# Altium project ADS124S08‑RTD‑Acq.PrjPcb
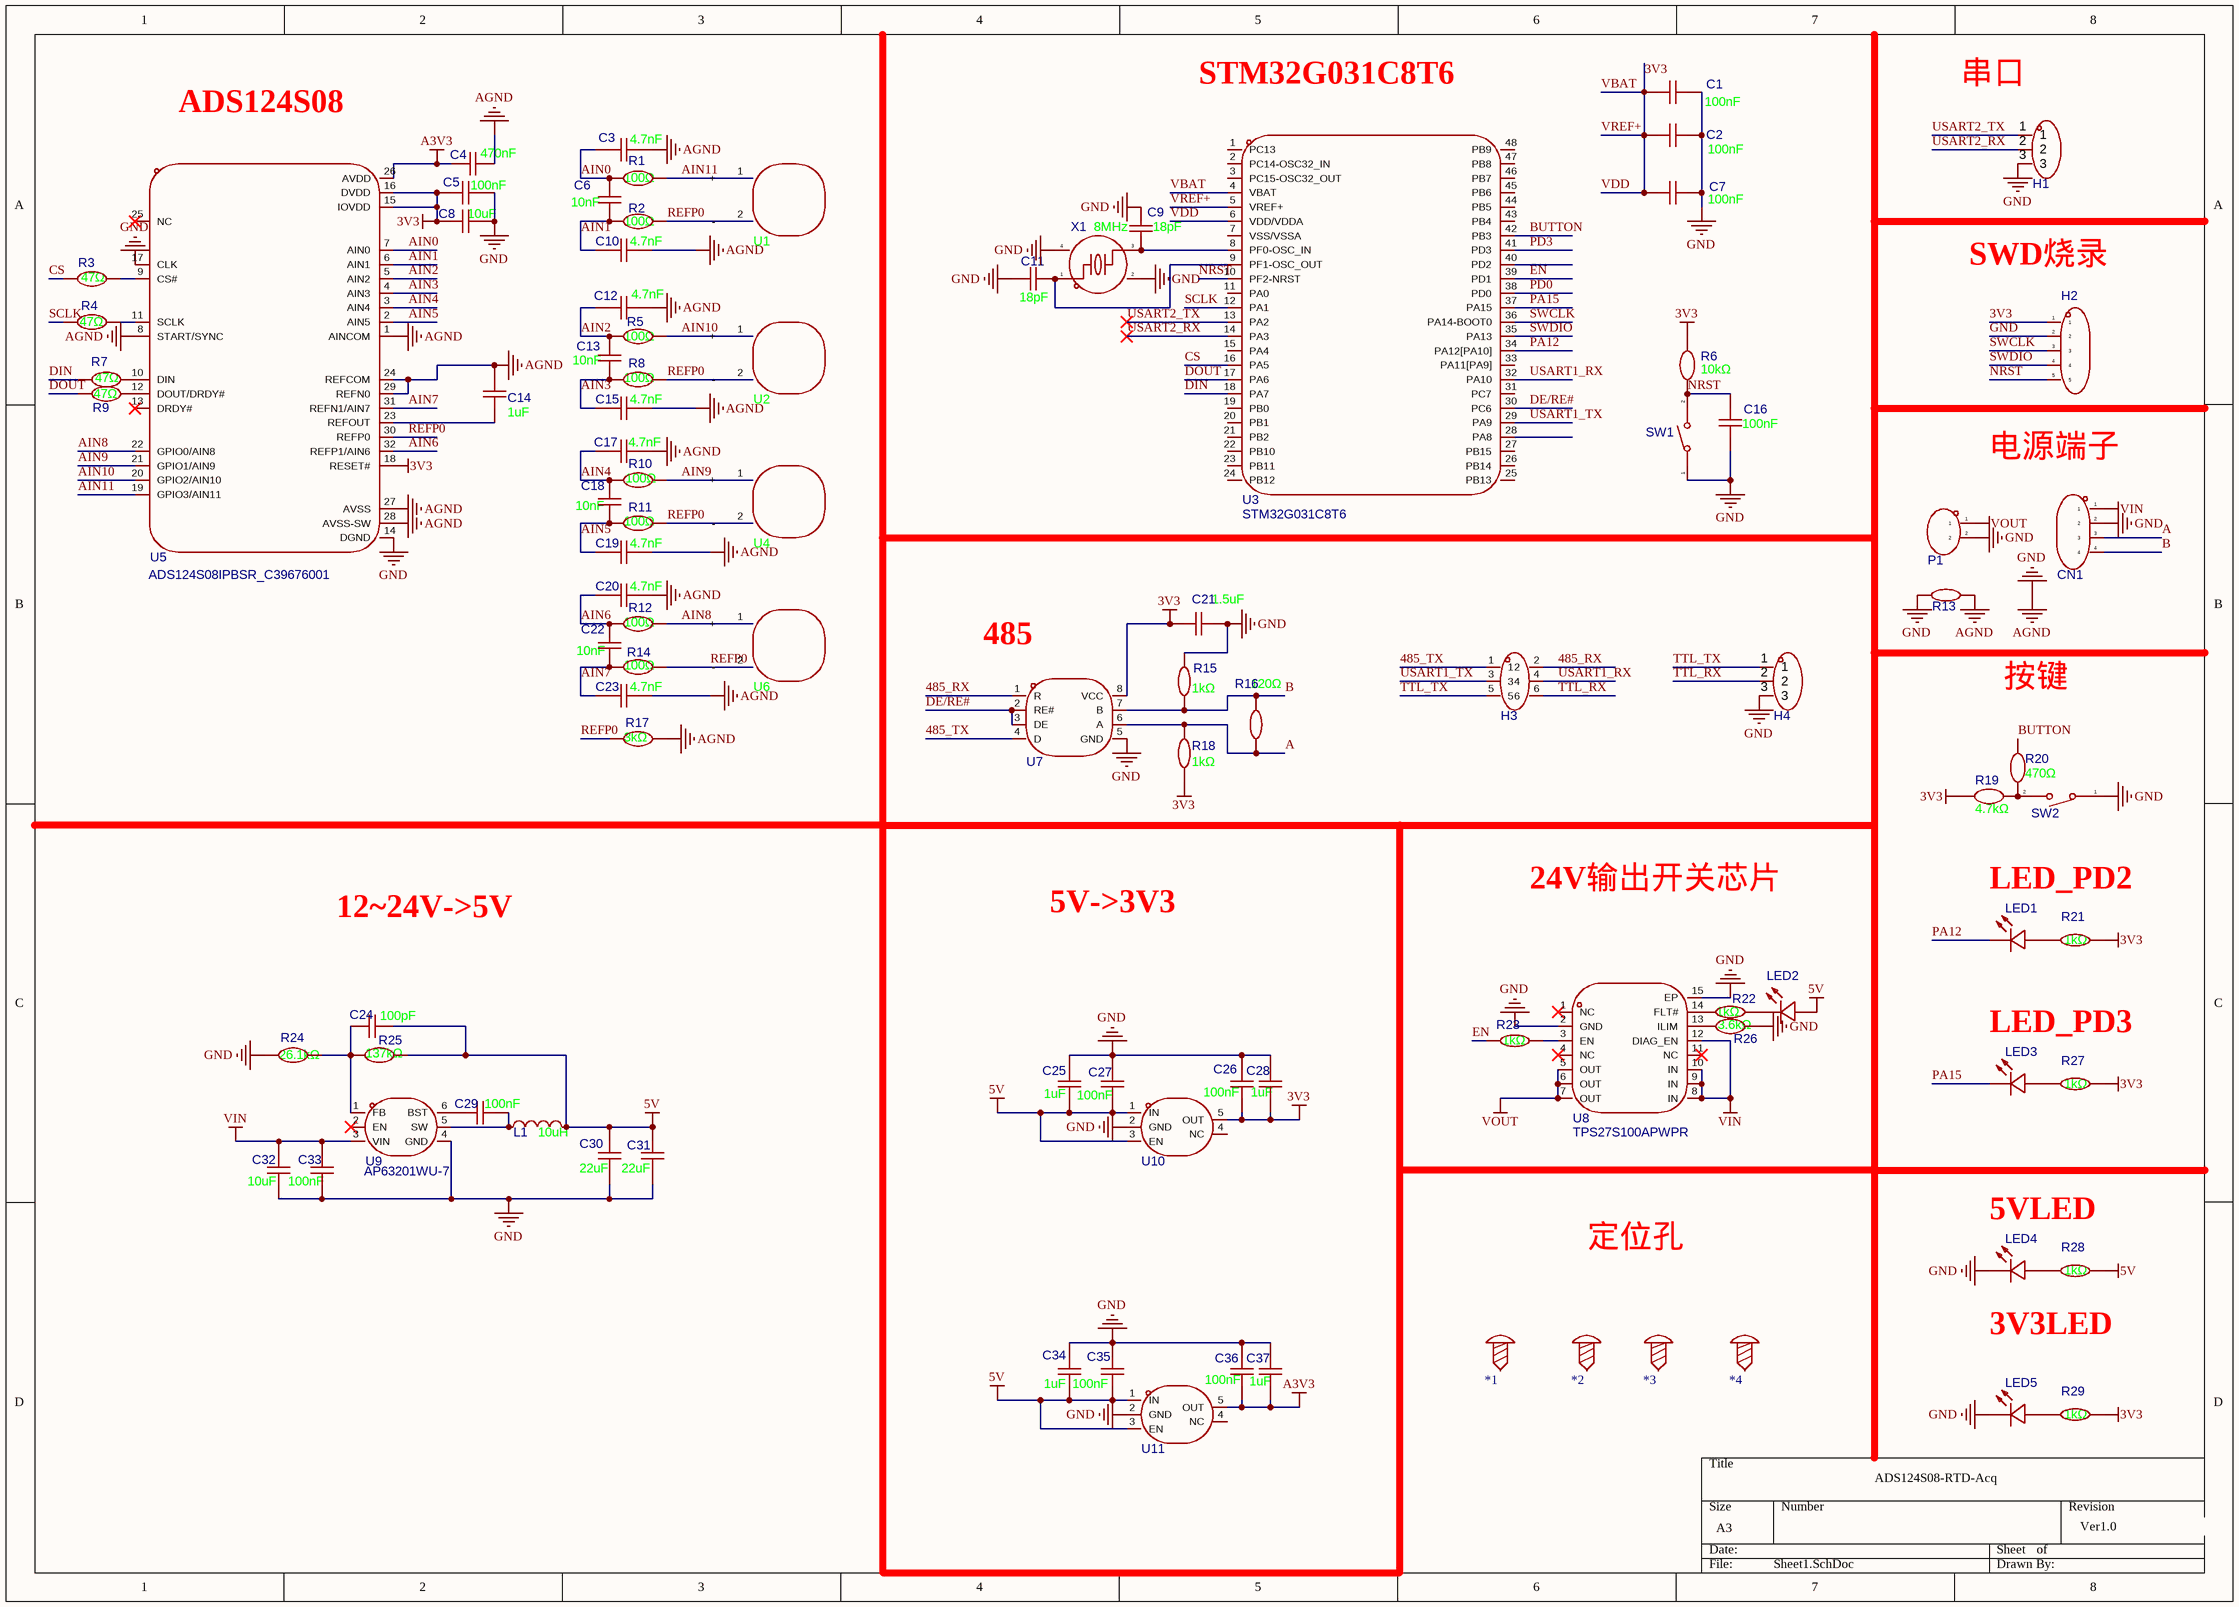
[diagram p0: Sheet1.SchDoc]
1 sheet, 96 parts. Net scope: global (net labels, ports and power ports of the same name join across sheets).
Board file: PCB1.PcbDoc

## Sheet Sheet1.SchDoc
size A3; SheetNumber: 1; SheetTotal: 1

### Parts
*1  螺丝孔_1  [M3螺丝]  (value not drawn)
*2  螺丝孔_1  [M3螺丝]  (value not drawn)
*3  螺丝孔_1  [M3螺丝]  (value not drawn)
*4  螺丝孔_1  [M3螺丝]  (value not drawn)
C1  value 100nF  [C0402]  (hidden comment: cc0402krx7r7bb104)
C2  value 100nF  [C0402]  (hidden comment: cc0402krx7r7bb104)
C3  value 4.7nF  [C0402]  (hidden comment: grm1555c1h472je01d)
C4  value 470nF  [C0603]  (hidden comment: cl10b474ka8nnnc)
C5  value 100nF  [C0402]  (hidden comment: cc0402krx7r7bb104)
C6  value 10nF  [C0805]  (hidden comment: cl21b103kbannnc)
C7  value 100nF  [C0402]  (hidden comment: cc0402krx7r7bb104)
C8  value 10uF  [C0603]  (hidden comment: hgc0603r5106m350nthj)
C9  value 18pF  [C0402]  (hidden comment: cc0402jrnpo9bn180)
C10  value 4.7nF  [C0402]  (hidden comment: grm1555c1h472je01d)
C11  value 18pF  [C0402]  (hidden comment: cc0402jrnpo9bn180)
C12  value 4.7nF  [C0402]  (hidden comment: grm1555c1h472je01d)
C13  value 10nF  [C0805]  (hidden comment: cl21b103kbannnc)
C14  value 1uF  [C0603]  (hidden comment: cga0603x5r105k500jt)
C15  value 4.7nF  [C0402]  (hidden comment: grm1555c1h472je01d)
C16  value 100nF  [C0402]  (hidden comment: cc0402krx7r7bb104)
C17  value 4.7nF  [C0402]  (hidden comment: grm1555c1h472je01d)
C18  value 10nF  [C0805]  (hidden comment: cl21b103kbannnc)
C19  value 4.7nF  [C0402]  (hidden comment: grm1555c1h472je01d)
C20  value 4.7nF  [C0402]  (hidden comment: grm1555c1h472je01d)
C21  value 1.5uF  [C0603]  (hidden comment: c1608x7r1a155kt000e)
C22  value 10nF  [C0805]  (hidden comment: cl21b103kbannnc)
C23  value 4.7nF  [C0402]  (hidden comment: grm1555c1h472je01d)
C24  value 100pF  [C0402]  (hidden comment: cc0402jrnpo9bn101)
C25  value 1uF  [C0603]  (hidden comment: cga0603x5r105k500jt)
C26  value 100nF  [C0402]  (hidden comment: cc0402krx7r7bb104)
C27  value 100nF  [C0402]  (hidden comment: cc0402krx7r7bb104)
C28  value 1uF  [C0603]  (hidden comment: cga0603x5r105k500jt)
C29  value 100nF  [C0603]  (hidden comment: cga0603x7r104k500jt)
C30  value 22uF  [C0603]  (hidden comment: hgc0603r5226m160nthj)
C31  value 22uF  [C0603]  (hidden comment: hgc0603r5226m160nthj)
C32  value 10uF  [C0603]  (hidden comment: hgc0603r5106m350nthj)
C33  value 100nF  [C0603]  (hidden comment: cga0603x7r104k500jt)
C34  value 1uF  [C0603]  (hidden comment: cga0603x5r105k500jt)
C35  value 100nF  [C0402]  (hidden comment: cc0402krx7r7bb104)
C36  value 100nF  [C0402]  (hidden comment: cc0402krx7r7bb104)
C37  value 1uF  [C0603]  (hidden comment: cga0603x5r105k500jt)
CN1  wj15edgrc-3.81-04p-14-00a  [CONN-TH_WJ15EDGRC-3.81-4P]  (value not drawn)
H1  lail-pz2.54-3p-l  [HDR-TH_3P-P2.54-V-M-1]  (value not drawn)
H2  pz254v-11-05p  [HDR-TH_5P-P2.54-V-M]  (value not drawn)
H3  pz254v-12-6p  [HDR-TH_6P-P2.54-V-M-R2-C3-S2.54]  (value not drawn)
H4  lail-pz2.54-3p-l  [HDR-TH_3P-P2.54-V-M-1]  (value not drawn)
L1  value 10uH  [IND-SMD_L4.0-W4.0]  (hidden comment: wpn4020h100mt)
LED1  ltst-c190kskt  [LED0603-RD]  (value not drawn)
LED2  ltst-c190kskt  [LED0603-RD]  (value not drawn)
LED3  ltst-c190kskt  [LED0603-RD]  (value not drawn)
LED4  ltst-c190kskt  [LED0603-RD]  (value not drawn)
LED5  ltst-c190kskt  [LED0603-RD]  (value not drawn)
P1  wj15edgrc-3.81-02p-14-00a  [CONN-TH_2P-P3.81_WJ15EDGRC-3.81-2P]  (value not drawn)
R1  value 100Ω  [R0603]  (hidden comment: frc0603f1000ts)
R2  value 100Ω  [R0603]  (hidden comment: frc0603f1000ts)
R3  value 47Ω  [R0402]  (hidden comment: frc0402f47r0ts)
R4  value 47Ω  [R0402]  (hidden comment: frc0402f47r0ts)
R5  value 100Ω  [R0603]  (hidden comment: frc0603f1000ts)
R6  value 10kΩ  [R0603]  (hidden comment: frc0603f1002ts)
R7  value 47Ω  [R0402]  (hidden comment: frc0402f47r0ts)
R8  value 100Ω  [R0603]  (hidden comment: frc0603f1000ts)
R9  value 47Ω  [R0402]  (hidden comment: frc0402f47r0ts)
R10  value 100Ω  [R0603]  (hidden comment: frc0603f1000ts)
R11  value 100Ω  [R0603]  (hidden comment: frc0603f1000ts)
R12  value 100Ω  [R0603]  (hidden comment: frc0603f1000ts)
R13  0603waf0000t5e  [R0603]  (value not drawn)
R14  value 100Ω  [R0603]  (hidden comment: frc0603f1000ts)
R15  value 1kΩ  [R0402]  (hidden comment: 0402wgf1001tce)
R16  value 120Ω  [R0402]  (hidden comment: 0402wgf1200tce)
R17  value 3kΩ  [R0805]  (hidden comment: frc0805f3001ts)
R18  value 1kΩ  [R0402]  (hidden comment: 0402wgf1001tce)
R19  value 4.7kΩ  [R0603]  (hidden comment: frc0603f4701ts)
R20  value 470Ω  [R0603]  (hidden comment: frc0603j471 ts)
R21  value 1kΩ  [R0603]  (hidden comment: 0603waf1001t5e)
R22  value 1kΩ  [R0603]  (hidden comment: 0603waf1001t5e)
R23  value 1kΩ  [R0603]  (hidden comment: 0603waf1001t5e)
R24  value 26.1kΩ  [R0402]  (hidden comment: rt0402brd0726k1l)
R25  value 137kΩ  [R0402]  (hidden comment: frc0402f1373ts)
R26  value 3.6kΩ  [R0603]  (hidden comment: frc0603f3601ts)
R27  value 1kΩ  [R0603]  (hidden comment: 0603waf1001t5e)
R28  value 1kΩ  [R0603]  (hidden comment: 0603waf1001t5e)
R29  value 1kΩ  [R0603]  (hidden comment: 0603waf1001t5e)
SW1  ts-1088-ar02016  [SW-SMD_L3.9-W3.0-P4.45]  (value not drawn)
SW2  ts-1088-ar02016  [SW-SMD_L3.9-W3.0-P4.45]  (value not drawn)
U1  pt1000焊盘  [PT1000焊盘]  (value not drawn)
U2  pt1000焊盘  [PT1000焊盘]  (value not drawn)
U3  stm32g031c8t6  [LQFP-48_L7.0-W7.0-P0.50-LS9.0-BL]
U4  pt1000焊盘  [PT1000焊盘]  (value not drawn)
U5  ads124s08ipbsr_c39676001  [TQFP-32_L5.0-W5.0-P0.50-LS7.0-BL]
U6  pt1000焊盘  [PT1000焊盘]  (value not drawn)
U7  sn65hvd75dr  [SOIC-8_L4.9-W3.9-P1.27-LS6.0-BL]  (value not drawn)
U8  tps27s100apwpr  [TSSOP-14_L5.0-W4.4-P0.65-LS6.4-BL-EP]
U9  ap63201wu-7  [TSOT-23-6_L2.9-W1.6-P0.95-LS2.8-BR]
U10  tps7a2033pdbvr  [SOT-23-5_L2.9-W1.6-P0.95-LS2.8-BR]  (value not drawn)
U11  tps7a2033pdbvr  [SOT-23-5_L2.9-W1.6-P0.95-LS2.8-BR]  (value not drawn)
X1  value 8MHz  [CRYSTAL-SMD_4P-L3.2-W2.5-BL]  (hidden comment: x32258mob4si)

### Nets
3V3: C1.1 C2.1 C5.2 C7.1 C8.1 C21.2 C26.1 C28.1 H2.1 R6.2 R18.1 R19.2 R21.2 R27.2 R29.2 U3.4(VBAT) U3.5(VREF+) U3.6(VDD/VDDA) U5.15(IOVDD) U5.16(DVDD) U5.18(RESET#) U7.8(VCC) U10.5(OUT)  [also labelled VBAT, VDD, VREF+]
5V: C24.2 C25.1 C27.1 C30.2 C31.2 C34.1 C35.1 L1.2 LED2.2(+) R25.1 R28.2 U10.1(IN) U10.3(EN) U11.1(IN) U11.3(EN)
A3V3: C4.1 C36.1 C37.1 U5.26(AVDD) U11.5(OUT)
GND: C1.2 C2.2 C3.2 C4.2 C5.1 C7.2 C8.2 C9.2 C10.2 C11.1 C12.2 C14.2 C15.2 C16.1 C17.2 C19.2 C20.2 C21.1 C23.2 C25.2 C26.2 C27.2 C28.2 C30.1 C31.1 C32.1 C33.1 C34.2 C35.2 C36.2 C37.2 CN1.2 H1.3 H2.2 H4.3 LED4.1(-) LED5.1(-) P1.2 R13.1 R13.2 R15.2 R17.2 R24.1 R26.2 SW1.1 SW2.1 U5.1(AINCOM) U5.8(START/SYNC) U5.14(DGND) U5.17(CLK) U5.24(REFCOM) U5.27(AVSS) U5.28(AVSS-SW) U5.29(REFN0) U7.5(GND) U8.2(GND) U8.15(EP) U9.4(GND) U10.2(GND) U11.2(GND) X1.2(GND) X1.4(GND)  [also labelled AGND]
VIN: C32.2 C33.2 CN1.1 U8.8(IN) U8.9(IN) U8.10(IN) U8.12(DIAG_EN) U9.3(VIN)
VOUT: P1.1 U8.5(OUT) U8.6(OUT) U8.7(OUT)
485_RX: H3.2 U7.1(R)
485_TX: H3.1 U7.4(D)
A: CN1.3 R16.1 R18.2 U7.6(A)
AIN0: C3.1 C6.2 R1.1 U5.7(AIN0)
AIN1: C6.1 C10.1 R2.1 U5.6(AIN1)
AIN2: C12.1 C13.2 R5.1 U5.5(AIN2)
AIN3: C13.1 C15.1 R8.1 U5.4(AIN3)
AIN4: C17.1 C18.2 R10.1 U5.3(AIN4)
AIN5: C18.1 C19.1 R11.1 U5.2(AIN5)
AIN6: C20.1 C22.2 R12.1 U5.32(REFP1/AIN6)
AIN7: C22.1 C23.1 R14.1 U5.31(REFN1/AIN7)
AIN8: R12.2 U5.22(GPIO0/AIN8) U6.1(+)
AIN9: R10.2 U4.1(+) U5.21(GPIO1/AIN9)
AIN10: R5.2 U2.1(+) U5.20(GPIO2/AIN10)
AIN11: R1.2 U1.1(+) U5.19(GPIO3/AIN11)
B: CN1.4 R15.1 R16.2 U7.7(B)
BUTTON: R20.1 U3.42(PB3)
CS: R3.1 U3.16(PA5)
DE/RE#: U3.30(PC6) U7.2(RE#) U7.3(DE)
DIN: R7.1 U3.18(PA7)
DOUT: R9.1 U3.17(PA6)
EN: R23.1 U3.39(PD1)
NRST: C16.2 H2.5 R6.1 SW1.2 U3.10(PF2-NRST)
PA12: LED1.1(-) U3.34(PA12[PA10])
PA15: LED3.1(-) U3.37(PA15)
PD0: U3.38(PD0)
PD3: U3.41(PD3)
REFP0: R2.2 R8.2 R11.2 R14.2 R17.1 U1.2(-) U2.2(-) U4.2(-) U5.30(REFP0) U6.2(-)
SCLK: R4.1 U3.12(PA1)
SWCLK: H2.3 U3.36(PA14-BOOT0)
SWDIO: H2.4 U3.35(PA13)
TTL_RX: H3.6 H4.2
TTL_TX: H3.5 H4.1
USART1_RX: H3.4 U3.32(PA10)
USART1_TX: H3.3 U3.29(PA9)
USART2_RX: H1.2 U3.14(PA3)
USART2_TX: H1.1 U3.13(PA2)
NetC9_1: C9.1 U3.8(PF0-OSC_IN) X1.3
NetC11_2: C11.2 U3.9(PF1-OSC_OUT) X1.1
NetC14_1: C14.1 U5.23(REFOUT)
NetC24_1: C24.1 R24.2 R25.2 U9.1(FB)
NetC29_1: C29.1 L1.1 U9.5(SW)
NetC29_2: C29.2 U9.6(BST)
NetLED1_2: LED1.2(+) R21.1
NetLED2_1: LED2.1(-) R22.2
NetLED3_2: LED3.2(+) R27.1
NetLED4_2: LED4.2(+) R28.1
NetLED5_2: LED5.2(+) R29.1
NetR3_2: R3.2 U5.9(CS#)
NetR4_2: R4.2 U5.11(SCLK)
NetR7_2: R7.2 U5.10(DIN)
NetR9_2: R9.2 U5.12(DOUT/DRDY#)
NetR19_1: R19.1 R20.2 SW2.2
NetR22_1: R22.1 U8.14(FLT#)
NetR23_2: R23.2 U8.3(EN)
NetR26_1: R26.1 U8.13(ILIM)

Not connected (* = marked no-connect by the designer): *1 1; *2 1; *3 1; *4 1; U3 1(PC13) 2(PC14-OSC32_IN) 3(PC15-OSC32_OUT) 7(VSS/VSSA) 11(PA0) 15(PA4) 19(PB0) 20(PB1) 21(PB2) 22(PB10) 23(PB11) 24(PB12) 25(PB13) 26(PB14) 27(PB15) 28(PA8) 31(PC7) 33(PA11[PA9]) 40(PD2) 43(PB4) 44(PB5) 45(PB6) 46(PB7) 47(PB8) 48(PB9); U5 13(DRDY#)* 25(NC)*; U8 1(NC)* 4(NC)* 11(NC)*; U9 2(EN)*; U10 4(NC); U11 4(NC)

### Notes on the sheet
- ADS124S08
- STM32G031C8T6
- 串口
- SWD烧录
- 电源端子
- (near U7) 485
- 按键
- 24V输出开关芯片
- LED_PD2
- 12|4V->5V
- 5V->3V3
- LED_PD3
- 定位孔
- 5VLED
- 3V3LED
- ADS124S08‑RTD‑Acq
- Ver1.0

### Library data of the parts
C1 C2 C5 C7 C16 C26 C27 C35 C36 = cc0402krx7r7bb104: 容值:100nF;精度:±10%;额定电压:16V;温度系数:X7R;; Manufacturer: YAGEO(国巨); AddInBom: yes; ModelId: 36a51122f27c49738f86b3bfa98863e0; ModelName: C0402_L1.0-W0.5-H0.5; ModelTransform: 39.37,19.685,0,0,0,0,0,0,0; Tolerance: ±10%; Voltage Rating: 16V; Temperature Coefficient: X7R
C3 C10 C12 C15 C17 C19 C20 C23 = grm1555c1h472je01d: 容值:4.7nF;精度:±5%;额定电压:50V;温度系数:C0G;; Manufacturer: muRata(村田); AddInBom: yes; ModelId: 36a51122f27c49738f86b3bfa98863e0; ModelName: C0402_L1.0-W0.5-H0.5; ModelTransform: 39.37,19.685,0,0,0,0,0,0,0; Tolerance: ±5%; Voltage Rating: 50V; Temperature Coefficient: C0G
C4 = cl10b474ka8nnnc: 容值:470nF;精度:±10%;额定电压:25V;温度系数:X7R;; Manufacturer: SAMSUNG(三星); AddInBom: yes; ModelId: ac125912035d415993ca9572d50418b1; ModelName: C0603_L1.6-W0.8-H0.8; ModelTransform: 62.992,31.496,0,0,0,0,0,0,0; Tolerance: ±10%; Voltage Rating: 25V; Temperature Coefficient: X7R
C6 C13 C18 C22 = cl21b103kbannnc: 容值:10nF;精度:±10%;额定电压:50V;温度系数:X7R;; Manufacturer: SAMSUNG(三星); AddInBom: yes; ModelId: 1ba041120af144c991958decab20d241; ModelName: C0805_L2.0-W1.3-H1.3; ModelTransform: 78.74,51.181,0,0,0,0,0,0.0005,0; Tolerance: ±10%; Voltage Rating: 50V; Temperature Coefficient: X7R
C8 C32 = hgc0603r5106m350nthj: 容值:10uF;精度:±20%;额定电压:35V;温度系数:X5R;; Manufacturer: Chinocera(华瓷); AddInBom: yes; ModelId: ac125912035d415993ca9572d50418b1; ModelName: C0603_L1.6-W0.8-H0.8; ModelTransform: 62.992,31.496,0,0,0,0,0,0,0; Tolerance: ±20%; Voltage Rating: 35V; Temperature Coefficient: X5R
C9 C11 = cc0402jrnpo9bn180: 容值:18pF;精度:±5%;额定电压:50V;温度系数:NP0;; Manufacturer: YAGEO(国巨); AddInBom: yes; ModelId: 36a51122f27c49738f86b3bfa98863e0; ModelName: C0402_L1.0-W0.5-H0.5; ModelTransform: 39.37,19.685,0,0,0,0,0,0,0; Tolerance: ±5%; Voltage Rating: 50V; Temperature Coefficient: NP0
C14 C25 C28 C34 C37 = cga0603x5r105k500jt: 容值:1uF;精度:±10%;额定电压:50V;温度系数:X5R;; Manufacturer: HRE(芯声); AddInBom: yes; ModelId: ac125912035d415993ca9572d50418b1; ModelName: C0603_L1.6-W0.8-H0.8; ModelTransform: 62.992,31.496,0,0,0,0,0,0,0; Tolerance: ±10%; Voltage Rating: 50V; Temperature Coefficient: X5R
C21 = c1608x7r1a155kt000e: 容值:1.5uF;精度:±10%;额定电压:10V;温度系数:X7R;; Manufacturer: TDK; AddInBom: yes; ModelId: ac125912035d415993ca9572d50418b1; ModelName: C0603_L1.6-W0.8-H0.8; ModelTransform: 62.992,31.496,0,0,0,0,0,0,0; Tolerance: ±10%; Voltage Rating: 10V; Temperature Coefficient: X7R
C24 = cc0402jrnpo9bn101: 容值:100pF;精度:±5%;额定电压:50V;温度系数:NP0;; Manufacturer: YAGEO(国巨); AddInBom: yes; ModelId: 36a51122f27c49738f86b3bfa98863e0; ModelName: C0402_L1.0-W0.5-H0.5; ModelTransform: 39.37,19.685,0,0,0,0,0,0,0; Tolerance: ±5%; Voltage Rating: 50V; Temperature Coefficient: NP0
C29 C33 = cga0603x7r104k500jt: 容值:100nF;精度:±10%;额定电压:50V;温度系数:X7R;; Manufacturer: HRE(芯声); AddInBom: yes; ModelId: ac125912035d415993ca9572d50418b1; ModelName: C0603_L1.6-W0.8-H0.8; ModelTransform: 62.992,31.496,0,0,0,0,0,0,0; Tolerance: ±10%; Voltage Rating: 50V; Temperature Coefficient: X7R
C30 C31 = hgc0603r5226m160nthj: 容值:22uF;精度:±20%;额定电压:16V;温度系数:X5R;; Manufacturer: Chinocera(华瓷); AddInBom: yes; ModelId: ac125912035d415993ca9572d50418b1; ModelName: C0603_L1.6-W0.8-H0.8; ModelTransform: 62.992,31.496,0,0,0,0,0,0,0; Tolerance: ±20%; Voltage Rating: 16V; Temperature Coefficient: X5R
CN1 = wj15edgrc-3.81-04p-14-00a: 连接器类型:板端/插座-闭口;固定方式:无固定装置;结构:1x4P;间距:3.81mm;颜色:绿色;安装方式:弯插;排数:1;每排PIN数:4;额定电流:8A;额定电压:300V;线规 - AWG:-;线规 - 平方毫米:-;工作温度:-40℃~+105℃;; Manufacturer: KANGNEX(康奈克斯电气); Symbol: WJ15EDGRC-3.81-4P; AddInBom: yes; ModelId: 4512f1cc0fee4248839d43b222858c36; ModelName: CONN-TH_4P_L16.1-W9.2-H7.0-P3.81; ModelTransform: 634.6483,360.2355,0,0,0,0,0,-117.126,-137.795; Number of Positions or Pins: 1x4P; Pitch: 3.81mm; Number of PINs Per Row: 4; Current Rating: 8A; Voltage Rating (Max): 300V
H1 H4 = lail-pz2.54-3p-l: 插针结构:1x3P;间距:2.54mm;圆针/方针:方针;排数:单排;总PIN位数:3P;额定电流:3A;额定电压:250V;塑高:2.5mm;端接针长度:3mm;触头材质:黄铜;触头镀层:金;工作温度:-25℃~+80℃;颜色:黑色;; Manufacturer: LAILAN(莱联); AddInBom: yes; ModelId: 94a8ffe137b6410295cb18cd3ffd99db; ModelName: HDR-M-2.54_1x3; ModelTransform: 299.9994,100,0,0,0,0,0,0,-118.11; Pin Structure: 1x3P; Pitch: 2.54mm; Circluar Pins/Square Pins: 方针; Current Rating: 3A; Voltage Rating (Max): 250V
H2 = pz254v-11-05p: 插针结构:1x5P;间距:2.54mm;行距:-;圆针/方针:方针;安装方式:直插;排数:单排;总PIN位数:5P;额定电流:3A;额定电压:250V;配合针长度:6mm;塑高:2.5mm;端接针长度:3mm;触头材质:黄铜;触头镀层:-;工作温度:-40℃~+105℃;颜色:黑色;; Manufacturer: XFCN(兴飞); AddInBom: yes; ModelId: 47d466e4a34f4fc5bc626cf773a24dd5; ModelName: HDR-TH_5P-P2.54-M-LI-1X5P; ModelTransform: 499.999,100,0,0,0,0,0,0,-118.11; Pin Structure: 1x5P; Pitch: 2.54mm; Circluar Pins/Square Pins: 方针; Current Rating: 3A; Voltage Rating (Max): 250V
H3 = pz254v-12-6p: 插针结构:2x3P;间距:2.54mm;行距:2.54mm;圆针/方针:方针;安装方式:直插;排数:双排;总PIN位数:6P;额定电流:3A;额定电压:-;配合针长度:6mm;塑高:2.5mm;端接针长度:3mm;触头材质:黄铜;触头镀层:金;工作温度:-40℃~+105℃;颜色:黑色;; Manufacturer: XFCN(兴飞); AddInBom: yes; ModelId: e22692306cbd4b5c8488f4142eed6b9c; ModelTransform: 300.3931,200,0,0,0,0,0,0,-118.11; Pin Structure: 2x3P; Pitch: 2.54mm; Circluar Pins/Square Pins: 方针; Current Rating: 3A
L1 = wpn4020h100mt: 电感值:10uH;精度:±20%;额定电流:2A;饱和电流(Isat):3.5A;类型:-;; Manufacturer: Sunlord(顺络); AddInBom: yes; ModelId: 45bc3737ecfd4f3bb122605ee525b018; ModelName: IND-SMD_L4.0-W4.0-H1.9; ModelTransform: 157.48,157.484,0,0,0,0,0,0,0; Tolerance: ±20%; Current Rating: 2A; Current - Saturation(Isat): 3.5A; DC Resistance(DCR): 216mΩ
LED1-LED5 = ltst-c190kskt: 灯头类型:-;发光颜色:黄色;正向压降(Vf):2.1V;功率:75mW;正向电流:20mA;波长:584.5nm~597nm;二极管配置:独立二极管;透镜颜色:无色透明透镜;色温:-;发光强度:104mcd;发光角度:130°;载带方式:-;工作温度:-30℃~+85℃;; Manufacturer: LITEON(光宝); AddInBom: yes; ModelId: 1f0d29a91be547639d425604e9b96ebb; ModelTransform: 63.7794,32.283,0,0,0,0,0,0,0; Illumination Color: 黄色; Voltage - Forward(Vf): 2.1V; Power(Watts): 75mW; Forward Current: 20mA; Peak Wavelength: 588nm; Diode Configuration: 独立二极管; Lens Color: 无色透明透镜; Luminous Intensity: 104mcd; Viewing Angle: 130°
P1 = wj15edgrc-3.81-02p-14-00a: 连接器类型:板端/插座-闭口;固定方式:无固定装置;结构:1x2P;间距:3.81mm;颜色:绿色;安装方式:弯插;排数:1;每排PIN数:2;额定电流:8A;额定电压:300V;线规 - AWG:-;线规 - 平方毫米:-;工作温度:-40℃~+105℃;; Manufacturer: KANGNEX(康奈克斯电气); Symbol: WJ15EDGRC-3.81-2P; AddInBom: yes; ModelId: 816ec8aca6fe4785be70cb4c5121258d; ModelName: CONN-TH_2P_L8.5-W9.2-H7.0-P3.81; ModelTransform: 334.645,360.2355,0,0,0,0,0,-118.11,-137.795; Number of Positions or Pins: 1x2P; Pitch: 3.81mm; Number of PINs Per Row: 2; Current Rating: 8A; Voltage Rating (Max): 300V
R1 R2 R5 R8 R10-R12 R14 = frc0603f1000ts: 电阻类型:厚膜电阻;阻值:100Ω;精度:±1%;功率:100mW;工作电压:75V;温度系数:±100ppm/℃;; Manufacturer: FOJAN(富捷); AddInBom: yes; ModelId: fc143cca1e79419f9cd78b61e9279f08; ModelTransform: 31.8897,63.7794,0,90,0,0,0,0,0; Tolerance: ±1%; Power(Watts): 100mW; Voltage-Supply(Max): 75V
R3 R4 R7 R9 = frc0402f47r0ts: 电阻类型:厚膜电阻;阻值:47Ω;精度:±1%;功率:62.5mW;工作电压:50V;温度系数:±100ppm/℃;; Manufacturer: FOJAN(富捷); AddInBom: yes; ModelId: 98c88bc2b9094f218f3a3e30a7012738; ModelName: R0402_L1.0-W0.5-H0.4; ModelTransform: 39.37,19.685,0,0,0,0,0,0,0; Tolerance: ±1%; Power(Watts): 62.5mW; Voltage-Supply(Max): 50V
R6 = frc0603f1002ts: 电阻类型:厚膜电阻;阻值:10kΩ;精度:±1%;功率:100mW;工作电压:75V;温度系数:±100ppm/℃;; Manufacturer: FOJAN(富捷); AddInBom: yes; ModelId: fc143cca1e79419f9cd78b61e9279f08; ModelTransform: 31.8897,63.7794,0,90,0,0,0,0,0; Tolerance: ±1%; Power(Watts): 100mW; Voltage-Supply(Max): 75V
R13 = 0603waf0000t5e: 电阻类型:厚膜电阻;阻值:0Ω;精度:±1%;功率:100mW;工作电压:75V;温度系数:-;; Manufacturer: UNI-ROYAL(厚声); AddInBom: yes; ModelId: fc143cca1e79419f9cd78b61e9279f08; ModelTransform: 31.8897,63.7794,0,90,0,0,0,0,0; Value: 0Ω; Tolerance: ±1%; Power(Watts): 100mW; Voltage-Supply(Max): 75V
R15 R18 = 0402wgf1001tce: 电阻类型:厚膜电阻;阻值:1kΩ;精度:±1%;功率:62.5mW;工作电压:50V;温度系数:±100ppm/℃;; Manufacturer: UNI-ROYAL(厚声); AddInBom: yes; ModelId: 98c88bc2b9094f218f3a3e30a7012738; ModelName: R0402_L1.0-W0.5-H0.4; ModelTransform: 39.37,19.685,0,0,0,0,0,0,0; Tolerance: ±1%; Power(Watts): 62.5mW; Voltage-Supply(Max): 50V
R16 = 0402wgf1200tce: 电阻类型:厚膜电阻;阻值:120Ω;精度:±1%;功率:62.5mW;工作电压:50V;温度系数:±100ppm/℃;; Manufacturer: UNI-ROYAL(厚声); AddInBom: yes; ModelId: 98c88bc2b9094f218f3a3e30a7012738; ModelName: R0402_L1.0-W0.5-H0.4; ModelTransform: 39.37,19.685,0,0,0,0,0,0,0; Tolerance: ±1%; Power(Watts): 62.5mW; Voltage-Supply(Max): 50V
R17 = frc0805f3001ts: 电阻类型:厚膜电阻;阻值:3kΩ;精度:±1%;功率:125mW;工作电压:150V;温度系数:±100ppm/℃;; Manufacturer: FOJAN(富捷); AddInBom: yes; ModelId: 37a81e68749a4138bd2dfa6897b24b85; ModelName: R0805_L2.0-W1.3-H0.6; ModelTransform: 78.74,51.181,0,0,0,0,0,-0.0005,0; Tolerance: ±1%; Power(Watts): 125mW; Voltage-Supply(Max): 150V
R19 = frc0603f4701ts: 电阻类型:厚膜电阻;阻值:4.7kΩ;精度:±1%;功率:100mW;工作电压:75V;温度系数:±100ppm/℃;; Manufacturer: FOJAN(富捷); AddInBom: yes; ModelId: fc143cca1e79419f9cd78b61e9279f08; ModelTransform: 31.8897,63.7794,0,90,0,0,0,0,0; Tolerance: ±1%; Power(Watts): 100mW; Voltage-Supply(Max): 75V
R20 = frc0603j471 ts: 电阻类型:厚膜电阻;阻值:470Ω;精度:±5%;功率:100mW;工作电压:75V;温度系数:±100ppm/℃;; Manufacturer: FOJAN(富捷); AddInBom: yes; ModelId: fc143cca1e79419f9cd78b61e9279f08; ModelTransform: 31.8897,63.7794,0,90,0,0,0,0,0; Tolerance: ±5%; Power(Watts): 100mW; Voltage-Supply(Max): 75V
R21-R23 R27-R29 = 0603waf1001t5e: 电阻类型:厚膜电阻;阻值:1kΩ;精度:±1%;功率:100mW;工作电压:75V;温度系数:±100ppm/℃;; Manufacturer: UNI-ROYAL(厚声); AddInBom: yes; ModelId: fc143cca1e79419f9cd78b61e9279f08; ModelTransform: 31.8897,63.7794,0,90,0,0,0,0,0; Tolerance: ±1%; Power(Watts): 100mW; Voltage-Supply(Max): 75V
R24 = rt0402brd0726k1l: 电阻类型:薄膜电阻;阻值:26.1kΩ;精度:±0.1%;功率:62.5mW;工作电压:50V;温度系数:±25ppm/℃;; Manufacturer: YAGEO(国巨); AddInBom: yes; ModelId: 98c88bc2b9094f218f3a3e30a7012738; ModelName: R0402_L1.0-W0.5-H0.4; ModelTransform: 39.37,19.685,0,0,0,0,0,0,0; Tolerance: ±0.1%; Power(Watts): 62.5mW; Voltage-Supply(Max): 50V
R25 = frc0402f1373ts: 电阻类型:厚膜电阻;阻值:137kΩ;精度:±1%;功率:62.5mW;工作电压:50V;温度系数:±100ppm/℃;; Manufacturer: FOJAN(富捷); AddInBom: yes; ModelId: 98c88bc2b9094f218f3a3e30a7012738; ModelName: R0402_L1.0-W0.5-H0.4; ModelTransform: 39.37,19.685,0,0,0,0,0,0,0; Tolerance: ±1%; Power(Watts): 62.5mW; Voltage-Supply(Max): 50V
R26 = frc0603f3601ts: 电阻类型:厚膜电阻;阻值:3.6kΩ;精度:±1%;功率:100mW;工作电压:75V;温度系数:±100ppm/℃;; Manufacturer: FOJAN(富捷); AddInBom: yes; ModelId: fc143cca1e79419f9cd78b61e9279f08; ModelTransform: 31.8897,63.7794,0,90,0,0,0,0,0; Tolerance: ±1%; Power(Watts): 100mW; Voltage-Supply(Max): 75V
SW1 SW2 = ts-1088-ar02016: 电路结构:单刀单掷;按钮形状:圆形按钮;作用力:1.6N;安装方式:立贴;开关长度:3.9mm;开关宽度:3mm;开关高度:2mm;带支架:不带支架;触点电流:50mA;额定电压:12V;带灯:-;工作寿命:10万次;; Manufacturer: XUNPU(讯普); AddInBom: yes; ModelId: b26698b69f274ffabef8a26c7d0e5dd1; ModelName: SW-SMD_L3.9-W2.9-H2.0-LS4.8; ModelTransform: 188.976,114.174,0,0,0,0,0,0,0; Circuit: 单刀单掷; Actuator Style: 圆形按钮; Operating Force: 1.6N; Switch Height: 2mm; with Bracket: 不带支架; Contact Current: 50mA; Voltage Rating: 12V; Actuator/Cap Color: 黑色; Life: 10万次
U1 U2 U4 U6 = pt1000焊盘: AddInBom: yes
U3 = stm32g031c8t6: CPU内核:ARM Cortex-M0+;CPU最大主频:64MHz;CPU位数:32 Bit;; Manufacturer: ST(意法半导体); AddInBom: yes; ModelId: 093be70396ff421eb2cdb946d5311efc; ModelName: LQFP-48_L7.0-W7.0-H1.4-LS9.0-P0.50; ModelTransform: 354.331,354.331,0,0,0,0,0,0,0; CPU Maximum Speed: 64MHz; Core Size: 32 Bit; Program Storage Size: 64KB; Program Memory Type: FLASH; RAM Size: 8KB; Number of I/O: 44; ADC (Bit): 12bit; Oscillator Type: 内置+外置; Voltage - Supply: 1.7V~3.6V
U5 = ads124s08ipbsr_c39676001: 分辨率(位):24;采样率:4kHz;工作电压:2.7V~5.25V;接口类型:SPI;; Manufacturer: TI(德州仪器); AddInBom: yes; ModelId: 0723864a05e7424ab80b3c78d6a7d93a; ModelName: TQFP-32_L5.0-W5.0-H1.2-LS7.0-P0.50; ModelTransform: 277.58783,277.58783,0,90,0,0,0.013,0,0; Resolution (Bits): 24; Sampling Rate: 4kHz; number of channels: 12; Interface: SPI; differential input: 是; Clock/Oscillator: 内置; Clock Frequency: 4.096MHz; Programmable Gain: 支持; Quiescent Current (Iq): 280uA
U7 = sn65hvd75dr: 类型:收发器;数据速率:20Mbps;; Manufacturer: TI(德州仪器); AddInBom: yes; ModelId: e81d2f7d937b4a6ab1dca543ff5d56a4; ModelName: SOIC-8_L4.9-W3.9-H1.7-LS6.0-P1.27; ModelTransform: 192.913,236.22,0,0,0,0,0,0,0; Number of Drivers: 1; Voltage - Supply: 3V~3.6V; Data Rate: 20Mbps; Number of Nodes: 213; ESD Protect: ±15kV; Quiescent Supply Current: 950uA; Communication Mode: 半双工
U8 = tps27s100apwpr: 类型:高侧开关;通道数:1;输入控制逻辑:高电平有效;工作电压:3.5V~40V;最大连续电流:4A;导通电阻:80mΩ;; Manufacturer: TI(德州仪器); AddInBom: yes; ModelId: 02f1f60386074b2ca8e111040ac061f2; ModelName: TSSOP-14_L5.0-W4.4-H1.0-LS6.4-P0.65; ModelTransform: 236.714,196.85,0,90,0,0,0,0.0005,0; Number of Channels: 1; Control Input Logic: 高电平有效; Maximum Continuous Current: 4A; RDS(on): 80mΩ
U9 = ap63201wu-7: 功能类型:降压型;工作电压:3.8V~32V;输出电压:-;输出电流:2A;输出类型:可调;; Manufacturer: DIODES(美台); AddInBom: yes; ModelId: 2c4039b5b88644c1bda4b4ba9e971667; ModelName: TSOT-23-6_L2.9-W1.6-H1.1-LS2.8-P0.95; ModelTransform: 110.45568,114.173,0,180,0,0,-0.005,-0.0005,0; Function: 降压型; Output Current: 2A; Frequency - Switching: 500kHz; Synchronous Rectifier: 是; Number of Outputs: 1; Topology: 降压式; Quiescent Current: 22uA; Switch tube (built-in/external): 内置; Output Type: 可调
U10 U11 = tps7a2033pdbvr: 输出类型:固定;最大输入电压:6V;输出电压:3.3V;输出电流:300mA;输出极性:正极;; Manufacturer: TI(德州仪器); AddInBom: yes; ModelId: 7ba65df16e7b4570af156e925f9c37fe; ModelTransform: 114.173,114.173,0,90,0,0,0,0,0; Output Type: 固定; Maximum Input Voltage: 6V; Output Voltage: 3.3V; Output Current: 300mA; Dropout Voltage: 140mV@(300mA); standby current: 15uA; Output Polarity: 正极; Number of Outputs: 1
X1 = x32258mob4si: 晶振类型:贴片晶振;频率:8MHz;常温频差:±10ppm;负载电容:12pF;频率稳定度:±20ppm;; Manufacturer: YXC(扬兴晶振); AddInBom: yes; ModelId: ff2dfd5650294453a14147960efe1838; ModelTransform: 125.984,98.425,0,0,0,0,0,0,0; Normal temperature Frequency Tolerance: ±10ppm; Load Capacitance: 12pF; Frequency Stability: ±20ppm; Equivalent Series Resistance(ESR): 180Ω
